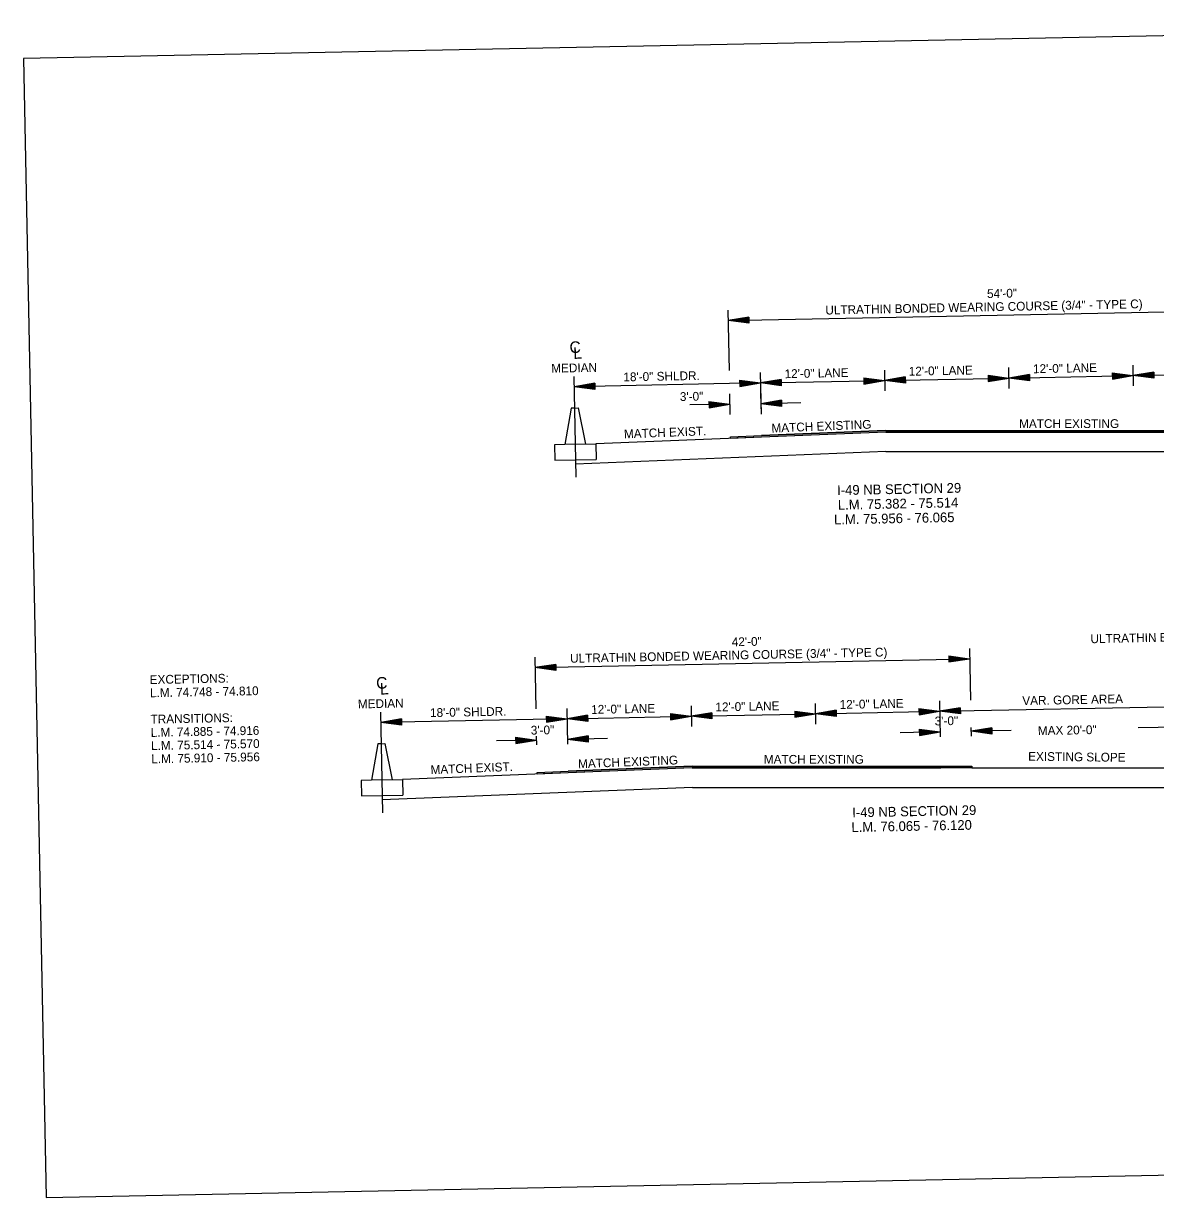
# Model space of a CAD drawing. Extents: x 174 to 869, y -36 to 177.
# Drawn here: x 347.9 to 457.2, y 57.1 to 170.5 of the extents above; entities that cross this region are included whole.
import ezdxf

# ---------------------------------------------------------------- set-up
doc = ezdxf.new("R2010")
doc.units = 0
for name, color, linetype in [('DSN_DRFT_Common-Annotations', 7, 'Continuous'), ('DSN_DRFT_Common-Line', 7, 'Continuous'), ('DSN_DRFT_Dimension', 7, 'Continuous')]:
    doc.layers.add(name, color=color, linetype=linetype)

msp = doc.modelspace()

# ---------------------------------------------------------------- linework, layer by layer
at = {"layer": 'DSN_DRFT_Common-Line'}
for p, q in [((415.94, 142.78), (416.05, 136.95)), ((443.05, 137.23), (443.09, 135.23)), ((455.05, 137.47), (455.09, 135.47)), ((401.06, 136.39), (401.26, 126.65)), ((419.06, 136.75), (419.14, 132.75)), ((431.06, 136.99), (431.1, 134.99)), ((416.1, 134.69), (416.14, 132.69)), ((419.1, 134.75), (419.14, 132.75)), ((400.79, 133.33), (400.19, 129.81)), ((401.12, 133.33), (400.79, 133.33)), ((401.12, 133.33), (401.46, 133.34)), ((401.46, 133.34), (402.19, 129.85)), ((431.18, 130.99), (403.19, 129.87)), ((431.17, 131.16), (419.18, 130.68)), ((431.17, 131.16), (467.18, 131.16)), ((431.18, 130.99), (467.18, 130.99)), ((401.19, 129.83), (399.19, 129.79)), ((399.19, 129.79), (399.22, 128.29)), ((401.19, 129.83), (403.19, 129.87)), ((403.19, 129.87), (403.22, 128.37)), ((399.22, 128.29), (403.22, 128.37)), ((431.21, 129.12), (401.23, 127.92)), ((431.21, 129.12), (485.19, 129.12)), ((439.27, 110.11), (439.37, 105.11)), ((397.28, 109.27), (397.38, 104.27)), ((400.38, 104.33), (400.45, 100.87)), ((412.38, 104.57), (412.42, 102.57)), ((424.37, 104.81), (424.41, 102.81)), ((436.37, 105.05), (436.44, 101.59)), ((382.38, 103.97), (382.58, 94.23)), ((439.42, 102.49), (439.44, 101.65)), ((382.11, 100.91), (381.51, 97.39)), ((382.44, 100.91), (382.11, 100.91)), ((382.44, 100.91), (382.78, 100.92)), ((382.78, 100.92), (383.51, 97.43)), ((397.43, 101.65), (397.45, 100.81)), ((412.49, 98.74), (400.5, 98.26)), ((412.49, 98.74), (436.5, 98.74)), ((439.5, 98.57), (439.5, 98.74)), ((412.5, 98.57), (384.51, 97.45)), ((412.5, 98.57), (436.5, 98.57)), ((439.5, 98.57), (460.51, 98.57)), ((382.51, 97.41), (380.51, 97.37)), ((380.51, 97.37), (380.54, 95.87)), ((382.51, 97.41), (384.51, 97.45)), ((412.53, 96.7), (382.55, 95.5)), ((384.51, 97.45), (384.54, 95.95)), ((412.53, 96.7), (499.37, 96.7)), ((380.54, 95.87), (384.54, 95.95))]:
    msp.add_line(p, q, dxfattribs=at)
for points in [[(347.89, 167.07), (350.09, 57.09), (520.05, 60.49), (517.85, 170.47)], [(467.18, 130.99), (431.18, 130.99), (419.18, 130.51), (416.19, 130.39), (416.18, 130.56), (419.18, 130.68), (431.17, 131.16), (467.18, 131.16), (470.08, 131.1), (470.07, 130.94)], [(436.5, 98.57), (412.5, 98.57), (400.5, 98.09), (397.5, 97.97), (397.5, 98.14), (400.5, 98.26), (412.49, 98.74), (436.5, 98.74), (439.5, 98.74), (439.5, 98.57)]]:
    msp.add_lwpolyline(points, close=True, dxfattribs=at)
at = {"layer": 'DSN_DRFT_Dimension'}
for p, q in [((415.96, 141.78), (469.95, 142.86)), ((417.95, 142.12), (415.96, 141.78)), ((417.96, 141.52), (415.96, 141.78)), ((417.95, 142.07), (416.29, 141.78)), ((417.96, 141.57), (416.29, 141.78)), ((417.95, 142.02), (416.64, 141.79)), ((417.96, 141.62), (416.64, 141.79)), ((417.95, 141.97), (416.97, 141.8)), ((417.96, 141.67), (416.97, 141.8)), ((417.96, 141.91), (417.31, 141.8)), ((417.96, 141.72), (417.31, 141.8)), ((417.96, 141.86), (417.64, 141.81)), ((417.96, 141.77), (417.64, 141.81)), ((417.95, 142.12), (417.96, 141.52)), ((421.07, 136.09), (419.08, 135.75)), ((421.07, 136.09), (421.08, 135.49)), ((429.07, 136.25), (431.08, 135.99)), ((429.07, 136.25), (429.08, 135.65)), ((429.07, 136.2), (430.74, 135.99)), ((429.07, 136.15), (430.4, 135.98)), ((429.07, 136.1), (430.07, 135.97)), ((433.07, 136.33), (431.08, 135.99)), ((431.08, 135.99), (443.07, 136.23)), ((433.07, 136.28), (431.41, 136)), ((433.07, 136.23), (431.75, 136.01)), ((433.07, 136.18), (432.09, 136.01)), ((433.07, 136.13), (432.43, 136.02)), ((433.08, 136.08), (432.76, 136.03)), ((433.07, 136.33), (433.08, 135.73)), ((441.07, 136.49), (443.07, 136.23)), ((441.07, 136.49), (441.08, 135.89)), ((441.07, 136.44), (442.74, 136.23)), ((441.07, 136.39), (442.4, 136.22)), ((441.07, 136.34), (442.06, 136.21)), ((441.07, 136.29), (441.72, 136.21)), ((441.07, 136.24), (441.39, 136.2)), ((441.08, 135.89), (443.07, 136.23)), ((441.08, 135.94), (442.74, 136.23)), ((441.08, 135.99), (442.4, 136.22)), ((441.08, 136.1), (441.72, 136.21)), ((441.08, 136.04), (442.06, 136.21)), ((441.08, 136.15), (441.39, 136.2)), ((445.07, 136.57), (443.07, 136.23)), ((443.07, 136.23), (455.07, 136.47)), ((445.08, 135.97), (443.07, 136.23)), ((445.07, 136.52), (443.41, 136.24)), ((445.08, 136.02), (443.41, 136.24)), ((445.07, 136.47), (443.75, 136.25)), ((445.08, 136.07), (443.75, 136.25)), ((445.07, 136.42), (444.08, 136.25)), ((445.08, 136.12), (444.08, 136.25)), ((445.07, 136.37), (444.42, 136.26)), ((445.08, 136.18), (444.42, 136.26)), ((445.07, 136.32), (444.76, 136.27)), ((445.07, 136.23), (444.76, 136.27)), ((445.07, 136.57), (445.08, 135.97)), ((453.07, 136.73), (455.07, 136.47)), ((453.07, 136.73), (453.08, 136.13)), ((453.07, 136.68), (454.74, 136.47)), ((453.07, 136.63), (454.39, 136.46)), ((453.07, 136.58), (454.06, 136.45)), ((453.07, 136.53), (453.72, 136.45)), ((453.07, 136.48), (453.39, 136.44)), ((453.07, 136.34), (453.72, 136.45)), ((453.07, 136.28), (454.06, 136.45)), ((453.07, 136.39), (453.39, 136.44)), ((453.08, 136.13), (455.07, 136.47)), ((453.08, 136.18), (454.74, 136.47)), ((453.08, 136.23), (454.39, 136.46)), ((457.07, 136.81), (455.07, 136.47)), ((455.07, 136.47), (467.07, 136.71)), ((457.08, 136.21), (455.07, 136.47)), ((457.07, 136.76), (455.41, 136.48)), ((457.08, 136.26), (455.41, 136.48)), ((457.07, 136.71), (455.75, 136.49)), ((457.08, 136.31), (455.75, 136.49)), ((457.07, 136.66), (456.08, 136.49)), ((457.07, 136.36), (456.08, 136.49)), ((457.07, 136.61), (456.42, 136.5)), ((457.07, 136.42), (456.42, 136.5)), ((457.07, 136.56), (456.76, 136.51)), ((457.07, 136.47), (456.76, 136.51)), ((457.07, 136.81), (457.08, 136.21)), ((419.08, 135.75), (401.08, 135.39)), ((403.08, 135.73), (401.08, 135.39)), ((403.09, 135.13), (401.08, 135.39)), ((403.08, 135.68), (401.42, 135.4)), ((403.09, 135.18), (401.42, 135.4)), ((403.08, 135.63), (401.76, 135.41)), ((403.09, 135.23), (401.76, 135.41)), ((403.08, 135.58), (402.09, 135.41)), ((403.08, 135.28), (402.09, 135.41)), ((403.08, 135.53), (402.43, 135.42)), ((403.08, 135.34), (402.43, 135.42)), ((403.08, 135.48), (402.77, 135.43)), ((403.08, 135.39), (402.77, 135.43)), ((403.08, 135.73), (403.09, 135.13)), ((417.07, 136.01), (419.08, 135.75)), ((417.07, 136.01), (417.09, 135.41)), ((417.07, 135.96), (418.74, 135.75)), ((417.08, 135.91), (418.4, 135.74)), ((417.08, 135.86), (418.07, 135.73)), ((417.08, 135.81), (417.73, 135.73)), ((417.08, 135.76), (417.4, 135.72)), ((417.08, 135.46), (418.74, 135.75)), ((417.08, 135.51), (418.4, 135.74)), ((417.08, 135.62), (417.73, 135.73)), ((417.08, 135.56), (418.07, 135.73)), ((417.08, 135.67), (417.4, 135.72)), ((417.09, 135.41), (419.08, 135.75)), ((419.08, 135.75), (431.08, 135.99)), ((421.08, 135.49), (419.08, 135.75)), ((421.07, 136.04), (419.41, 135.76)), ((421.08, 135.54), (419.41, 135.76)), ((421.07, 135.99), (419.76, 135.77)), ((421.08, 135.59), (419.76, 135.77)), ((421.08, 135.94), (420.09, 135.77)), ((421.08, 135.64), (420.09, 135.77)), ((421.08, 135.89), (420.43, 135.78)), ((421.08, 135.7), (420.43, 135.78)), ((421.08, 135.84), (420.76, 135.79)), ((421.08, 135.75), (420.76, 135.79)), ((429.07, 136.05), (429.73, 135.97)), ((429.08, 136), (429.39, 135.96)), ((429.08, 135.65), (431.08, 135.99)), ((429.08, 135.7), (430.74, 135.99)), ((429.08, 135.75), (430.4, 135.98)), ((429.08, 135.86), (429.73, 135.97)), ((429.08, 135.8), (430.07, 135.97)), ((429.08, 135.91), (429.39, 135.96)), ((433.08, 135.73), (431.08, 135.99)), ((433.08, 135.78), (431.41, 136)), ((433.08, 135.83), (431.75, 136.01)), ((433.08, 135.88), (432.09, 136.01)), ((433.08, 135.94), (432.43, 136.02)), ((433.08, 135.99), (432.76, 136.03)), ((414.11, 133.95), (416.12, 133.69)), ((414.11, 133.95), (414.13, 133.35)), ((414.11, 133.9), (415.79, 133.69)), ((414.12, 133.85), (415.44, 133.68)), ((414.12, 133.8), (415.11, 133.67)), ((421.11, 134.09), (419.12, 133.75)), ((422.98, 133.83), (419.12, 133.75)), ((421.11, 134.04), (419.45, 133.76)), ((421.11, 133.99), (419.8, 133.77)), ((421.12, 133.94), (420.13, 133.77)), ((421.12, 133.89), (420.47, 133.78)), ((421.12, 133.84), (420.8, 133.79)), ((421.12, 133.75), (420.8, 133.79)), ((421.11, 134.09), (421.12, 133.49)), ((416.12, 133.71), (412.25, 133.64)), ((414.12, 133.75), (414.77, 133.67)), ((414.12, 133.7), (414.44, 133.66)), ((414.12, 133.4), (415.79, 133.69)), ((414.12, 133.45), (415.44, 133.68)), ((414.12, 133.56), (414.77, 133.67)), ((414.12, 133.5), (415.11, 133.67)), ((414.12, 133.61), (414.44, 133.66)), ((414.13, 133.35), (416.12, 133.69)), ((421.12, 133.49), (419.12, 133.75)), ((421.12, 133.54), (419.45, 133.76)), ((421.12, 133.59), (419.8, 133.77)), ((421.12, 133.64), (420.13, 133.77)), ((421.12, 133.7), (420.47, 133.78)), ((397.3, 108.27), (439.29, 109.11)), ((437.29, 109.41), (439.29, 109.11)), ((437.29, 109.41), (437.29, 108.81)), ((437.29, 109.36), (438.96, 109.11)), ((437.29, 109.31), (438.61, 109.11)), ((437.29, 109.26), (438.28, 109.11)), ((437.29, 109.21), (437.94, 109.11)), ((437.29, 109.16), (437.61, 109.11)), ((437.29, 108.81), (439.29, 109.11)), ((437.29, 109.01), (437.94, 109.11)), ((437.29, 108.91), (438.61, 109.11)), ((437.29, 108.86), (438.96, 109.11)), ((437.29, 108.96), (438.28, 109.11)), ((437.29, 109.06), (437.61, 109.11)), ((399.3, 108.57), (397.3, 108.27)), ((399.3, 107.97), (397.3, 108.27)), ((399.3, 108.52), (397.63, 108.27)), ((399.3, 108.02), (397.63, 108.27)), ((399.3, 108.47), (397.98, 108.27)), ((399.3, 108.07), (397.98, 108.27)), ((399.3, 108.42), (398.31, 108.27)), ((399.3, 108.12), (398.31, 108.27)), ((399.3, 108.37), (398.65, 108.27)), ((399.3, 108.17), (398.65, 108.27)), ((399.3, 108.32), (398.98, 108.27)), ((399.3, 108.22), (398.98, 108.27)), ((399.3, 108.57), (399.3, 107.97)), ((434.39, 104.31), (436.39, 104.05)), ((434.39, 104.31), (434.4, 103.71)), ((436.39, 104.05), (461.39, 104.55)), ((438.38, 104.39), (436.39, 104.05)), ((438.39, 104.34), (436.72, 104.06)), ((438.38, 104.39), (438.4, 103.79)), ((400.4, 103.33), (382.4, 102.97)), ((384.4, 103.31), (382.4, 102.97)), ((384.4, 103.26), (382.74, 102.98)), ((384.4, 103.21), (383.08, 102.99)), ((384.4, 103.31), (384.41, 102.71)), ((398.39, 103.59), (400.4, 103.33)), ((398.39, 103.59), (398.4, 102.99)), ((398.39, 103.54), (400.06, 103.33)), ((398.39, 103.49), (399.72, 103.32)), ((398.4, 103.44), (399.39, 103.31)), ((398.4, 103.39), (399.05, 103.31)), ((398.4, 103.34), (398.71, 103.3)), ((398.4, 102.99), (400.4, 103.33)), ((398.4, 103.04), (400.06, 103.33)), ((398.4, 103.09), (399.72, 103.32)), ((398.4, 103.19), (399.05, 103.31)), ((398.4, 103.14), (399.39, 103.31)), ((398.4, 103.25), (398.71, 103.3)), ((402.39, 103.67), (400.4, 103.33)), ((400.4, 103.33), (412.4, 103.57)), ((402.4, 103.07), (400.4, 103.33)), ((402.39, 103.62), (400.73, 103.34)), ((402.4, 103.12), (400.73, 103.34)), ((402.39, 103.57), (401.08, 103.35)), ((402.4, 103.17), (401.08, 103.35)), ((402.39, 103.52), (401.41, 103.35)), ((402.4, 103.22), (401.41, 103.35)), ((402.4, 103.47), (401.75, 103.36)), ((402.4, 103.27), (401.75, 103.36)), ((402.4, 103.42), (402.08, 103.37)), ((402.4, 103.33), (402.08, 103.37)), ((402.39, 103.67), (402.4, 103.07)), ((410.39, 103.83), (412.4, 103.57)), ((410.39, 103.83), (410.4, 103.23)), ((410.39, 103.78), (412.06, 103.57)), ((410.39, 103.73), (411.72, 103.56)), ((410.39, 103.68), (411.38, 103.55)), ((410.39, 103.63), (411.05, 103.55)), ((410.4, 103.58), (410.71, 103.54)), ((410.4, 103.23), (412.4, 103.57)), ((410.4, 103.28), (412.06, 103.57)), ((410.4, 103.33), (411.72, 103.56)), ((410.4, 103.43), (411.05, 103.55)), ((410.4, 103.38), (411.38, 103.55)), ((410.4, 103.49), (410.71, 103.54)), ((414.39, 103.91), (412.4, 103.57)), ((412.4, 103.57), (424.39, 103.81)), ((414.4, 103.31), (412.4, 103.57)), ((414.39, 103.86), (412.73, 103.58)), ((414.4, 103.36), (412.73, 103.58)), ((414.39, 103.81), (413.07, 103.59)), ((414.4, 103.41), (413.07, 103.59)), ((414.39, 103.76), (413.41, 103.59)), ((414.4, 103.46), (413.41, 103.59)), ((414.39, 103.71), (413.75, 103.6)), ((414.4, 103.51), (413.75, 103.6)), ((414.39, 103.66), (414.08, 103.61)), ((414.4, 103.57), (414.08, 103.61)), ((414.39, 103.91), (414.4, 103.31)), ((422.39, 104.07), (424.39, 103.81)), ((422.39, 104.07), (422.4, 103.47)), ((422.39, 104.02), (424.06, 103.81)), ((422.39, 103.97), (423.72, 103.8)), ((422.39, 103.92), (423.38, 103.79)), ((422.39, 103.87), (423.04, 103.79)), ((422.39, 103.82), (422.71, 103.78)), ((422.39, 103.73), (422.71, 103.78)), ((422.4, 103.47), (424.39, 103.81)), ((422.4, 103.52), (424.06, 103.81)), ((422.4, 103.57), (423.72, 103.8)), ((422.4, 103.67), (423.04, 103.79)), ((422.4, 103.62), (423.38, 103.79)), ((426.39, 104.15), (424.39, 103.81)), ((424.39, 103.81), (436.39, 104.05)), ((426.4, 103.55), (424.39, 103.81)), ((426.39, 104.1), (424.73, 103.82)), ((426.4, 103.6), (424.73, 103.82)), ((426.39, 104.05), (425.07, 103.83)), ((426.4, 103.65), (425.07, 103.83)), ((426.39, 104), (425.4, 103.83)), ((426.4, 103.7), (425.4, 103.83)), ((426.39, 103.95), (425.74, 103.84)), ((426.39, 103.75), (425.74, 103.84)), ((426.39, 103.9), (426.08, 103.85)), ((426.39, 103.81), (426.08, 103.85)), ((426.39, 104.15), (426.4, 103.55)), ((434.39, 104.26), (436.06, 104.05)), ((434.39, 104.21), (435.71, 104.04)), ((434.39, 104.16), (435.38, 104.03)), ((434.39, 104.11), (435.04, 104.03)), ((434.39, 104.06), (434.71, 104.02)), ((434.39, 103.91), (435.04, 104.03)), ((434.39, 103.86), (435.38, 104.03)), ((434.39, 103.97), (434.71, 104.02)), ((434.4, 103.71), (436.39, 104.05)), ((434.4, 103.76), (436.06, 104.05)), ((434.4, 103.81), (435.71, 104.04)), ((438.4, 103.79), (436.39, 104.05)), ((438.4, 103.84), (436.72, 104.06)), ((438.39, 104.29), (437.07, 104.07)), ((438.39, 103.89), (437.07, 104.07)), ((438.39, 104.24), (437.4, 104.07)), ((438.39, 103.94), (437.4, 104.07)), ((438.39, 104.19), (437.74, 104.08)), ((438.39, 103.99), (437.74, 104.08)), ((438.39, 104.14), (438.07, 104.09)), ((438.39, 104.05), (438.07, 104.09)), ((384.41, 102.71), (382.4, 102.97)), ((384.41, 102.76), (382.74, 102.98)), ((384.41, 102.81), (383.08, 102.99)), ((384.4, 103.16), (383.41, 102.99)), ((384.4, 102.86), (383.41, 102.99)), ((384.4, 103.11), (383.75, 103)), ((384.4, 102.91), (383.75, 103)), ((384.4, 103.06), (384.09, 103.01)), ((384.4, 102.97), (384.09, 103.01)), ((436.43, 102.05), (432.57, 101.98)), ((434.43, 102.31), (436.43, 102.05)), ((434.43, 102.31), (434.44, 101.71)), ((434.43, 102.26), (436.1, 102.05)), ((434.43, 102.21), (435.75, 102.04)), ((434.43, 102.16), (435.42, 102.03)), ((434.43, 102.11), (435.08, 102.03)), ((434.43, 102.06), (434.75, 102.02)), ((434.44, 101.71), (436.43, 102.05)), ((434.44, 101.76), (436.1, 102.05)), ((441.42, 102.45), (439.43, 102.11)), ((443.29, 102.19), (439.43, 102.11)), ((441.44, 101.85), (439.43, 102.11)), ((441.42, 102.4), (439.76, 102.12)), ((441.43, 101.9), (439.76, 102.12)), ((441.43, 102.35), (440.11, 102.13)), ((441.43, 101.95), (440.11, 102.13)), ((441.43, 102.3), (440.44, 102.13)), ((441.43, 102), (440.44, 102.13)), ((441.43, 102.25), (440.78, 102.14)), ((441.43, 102.06), (440.78, 102.14)), ((441.43, 102.2), (441.11, 102.15)), ((441.43, 102.11), (441.11, 102.15)), ((441.42, 102.45), (441.44, 101.85)), ((459.43, 102.51), (455.56, 102.44)), ((397.44, 101.27), (393.57, 101.2)), ((395.43, 101.53), (397.44, 101.27)), ((395.43, 101.53), (395.44, 100.93)), ((395.43, 101.48), (397.1, 101.27)), ((395.43, 101.43), (396.76, 101.26)), ((395.44, 101.38), (396.43, 101.25)), ((395.44, 101.33), (396.09, 101.25)), ((395.44, 101.28), (395.75, 101.24)), ((395.44, 100.93), (397.44, 101.27)), ((395.44, 100.98), (397.1, 101.27)), ((395.44, 101.03), (396.76, 101.26)), ((395.44, 101.14), (396.09, 101.25)), ((395.44, 101.08), (396.43, 101.25)), ((395.44, 101.19), (395.75, 101.24)), ((402.43, 101.67), (400.44, 101.33)), ((404.3, 101.41), (400.44, 101.33)), ((402.44, 101.07), (400.44, 101.33)), ((402.43, 101.62), (400.77, 101.34)), ((402.44, 101.12), (400.77, 101.34)), ((402.43, 101.57), (401.12, 101.35)), ((402.44, 101.17), (401.12, 101.35)), ((402.43, 101.52), (401.45, 101.35)), ((402.44, 101.22), (401.45, 101.35)), ((402.44, 101.47), (401.79, 101.36)), ((402.44, 101.28), (401.79, 101.36)), ((402.44, 101.42), (402.12, 101.37)), ((402.44, 101.33), (402.12, 101.37)), ((402.43, 101.67), (402.44, 101.07)), ((434.43, 101.92), (435.08, 102.03)), ((434.43, 101.86), (435.42, 102.03)), ((434.43, 101.97), (434.75, 102.02)), ((434.44, 101.81), (435.75, 102.04))]:
    msp.add_line(p, q, dxfattribs=at)

# ---------------------------------------------------------------- texts
at = {"layer": 'DSN_DRFT_Common-Annotations'}
for s, height, rotation, p in [('54\'-0"', 0.85, 1.1458, (440.98, 143.95)), ('ULTRATHIN BONDED WEARING COURSE (3/4" - TYPE C)', 0.85, 1.1458, (425.36, 142.36)), ('C', 1.12, 2.2915, (400.66, 138.63)), ('L', 1.12, 2.2915, (401.02, 138.07)), ('MEDIAN', 0.85, 1.1458, (398.88, 136.74)), ('12\'-0" LANE', 0.85, 1.1458, (433.42, 136.45)), ('12\'-0" LANE', 0.85, 1.1458, (445.42, 136.69)), ('18\'-0" SHLDR.', 0.85, 1.1458, (405.85, 135.9)), ('12\'-0" LANE', 0.85, 1.1458, (421.42, 136.21)), (' 3\'-0"', 0.85, 1.1458, (410.99, 134)), ('MATCH EXIST.', 0.85, 2.2915, (405.91, 130.39)), ('MATCH EXISTING', 0.85, 2.2915, (420.16, 130.96)), ('I-49 NB SECTION 29', 0.943, 1.1458, (426.5, 124.92)), ('L.M. 75.382 - 75.514', 0.943, 1.1458, (426.57, 123.51)), ('L.M. 75.956 - 76.065', 0.943, 1.1458, (426.2, 122.09)), ('42\'-0"', 0.85, 1.1458, (416.32, 110.32)), ('ULTRATHIN BONDED WEARING COURSE (3/4" - TYPE C)', 0.85, 1.1458, (450.97, 110.62)), ('ULTRATHIN BONDED WEARING COURSE (3/4" - TYPE C)', 0.85, 1.1458, (400.7, 108.73)), ('EXCEPTIONS:', 0.85, 1.1458, (360.09, 106.67)), ('C', 1.12, 2.2915, (381.98, 106.21)), ('L', 1.12, 2.2915, (382.34, 105.65)), ('L.M. 74.748 - 74.810', 0.85, 1.1458, (360.12, 105.4)), ('VAR. GORE AREA', 0.85, 1.1458, (444.39, 104.64)), ('MEDIAN', 0.85, 1.1458, (380.2, 104.32)), ('18\'-0" SHLDR.', 0.85, 1.1458, (387.17, 103.48)), ('12\'-0" LANE', 0.85, 1.1458, (402.74, 103.79)), ('12\'-0" LANE', 0.85, 1.1458, (414.74, 104.03)), ('12\'-0" LANE', 0.85, 1.1458, (426.74, 104.27)), ('TRANSITIONS:', 0.85, 1.1458, (360.17, 102.85)), (' 3\'-0"', 0.85, 1.1458, (435.61, 102.67)), ('L.M. 74.885 - 74.916', 0.85, 1.1458, (360.19, 101.57)), (' 3\'-0"', 0.85, 1.1458, (396.59, 101.78)), ('MAX 20\'-0"', 0.85, 1.1458, (445.89, 101.74)), ('L.M. 75.514 - 75.570', 0.85, 1.1458, (360.22, 100.3)), ('L.M. 75.910 - 75.956', 0.85, 1.1458, (360.24, 99.02)), ('MATCH EXISTING', 0.85, 2.2915, (401.48, 98.54)), ('EXISTING SLOPE', 0.85, 359.3769, (444.94, 99.27)), ('MATCH EXIST.', 0.85, 2.2915, (387.23, 97.97)), ('I-49 NB SECTION 29', 0.943, 1.1458, (427.96, 93.8)), ('L.M. 76.065 - 76.120', 0.943, 1.1458, (427.88, 92.38))]:
    msp.add_text(s, height=height, rotation=rotation, dxfattribs=at).set_placement(p)
for p in [(444.07, 131.4), (419.41, 98.98)]:
    msp.add_text('MATCH EXISTING', height=0.85, dxfattribs=at).set_placement(p)

doc.saveas('drawing.dxf')
